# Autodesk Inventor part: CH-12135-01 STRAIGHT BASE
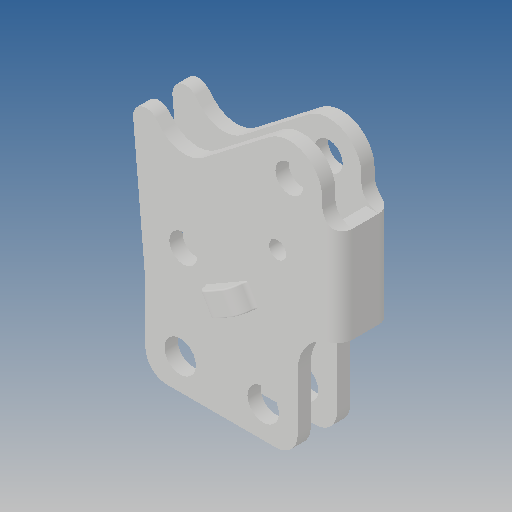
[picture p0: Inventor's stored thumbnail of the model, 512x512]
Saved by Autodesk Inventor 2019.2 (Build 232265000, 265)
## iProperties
Created: 2012-09
Part Number: CH-12135-01 STRAIGHT BASE
Material: Ogólny
Document SubType Name: Modeling
Designer: CADENGINEERING4
Density: 1 g/cm^3
Appearance: Domyślna
Author: CADENGINEERING4
Revision Number: ÈÎºÎ
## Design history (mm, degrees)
feature "ÇÐ³ý-À­Éì5"
node "Bryła1"
